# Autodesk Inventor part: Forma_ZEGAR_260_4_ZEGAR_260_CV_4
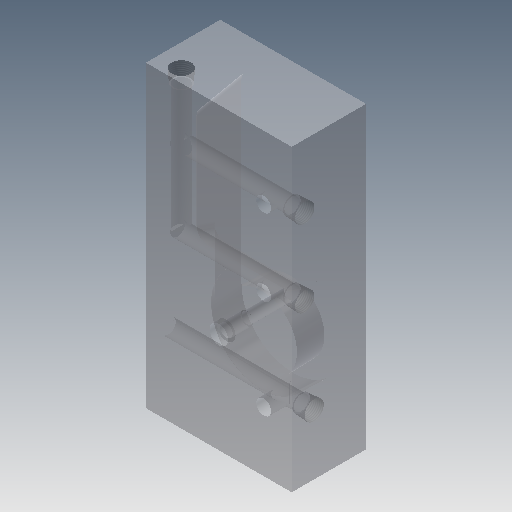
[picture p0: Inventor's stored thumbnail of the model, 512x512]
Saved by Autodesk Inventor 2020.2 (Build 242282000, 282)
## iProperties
Created: 2015-01
Part Number: Forma_ZEGAR_260_4_ZEGAR_260_CV_4
Material: Ogólny
Document SubType Name: Modeling
Designer: F.Stasiak
Density: 1 g/cm^3
Appearance: Domyślna
Catalog Web Link: www.expertbooks.pl
Manager: www.cadconsulting.pl
Company: Fabian Stasiak CAD Consulting
Author: F.Stasiak
Subject: Zbiór ćwiczeń. Autodesk Inventor 2020. Kurs Professional
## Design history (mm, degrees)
node "Forma_ZEGAR_260_4_ZEGAR_260_CV_Base"
feature "Rzeźbienie3"
feature "Rzeźbienie13"
feature "Gwint6" dims "d10" = 0, "d11" = 0
feature "Rzeźbienie14"
feature "Gwint7" dims "d12" = 0, "d13" = 0
feature "Rzeźbienie15"
feature "Gwint8" dims "d14" = 0, "d15" = 0
feature "Rzeźbienie16"
feature "Gwint9" dims "d16" = 0, "d17" = 0
feature "Rzeźbienie17"
feature "Rzeźbienie18"
feature "Rzeźbienie19"
feature "Bryła1::Forma_ZEGAR_260_4_ZEGAR_260_CV_Base"
tag "Bryła wyprowadzona1"
node "Bryła1"
feature "Forma_ZEGAR_260_4_ZEGAR_260_CV_Base_Bodies"
feature "Powierzchnia3"
body "Srf3"
feature "Powierzchnia13"
body "Srf13"
feature "Powierzchnia14"
body "Srf14"
feature "Powierzchnia15"
body "Srf15"
feature "Powierzchnia16"
body "Srf16"
feature "Powierzchnia17"
body "Srf17"
feature "Powierzchnia18"
body "Srf18"
feature "Powierzchnia19"
body "Srf19"
